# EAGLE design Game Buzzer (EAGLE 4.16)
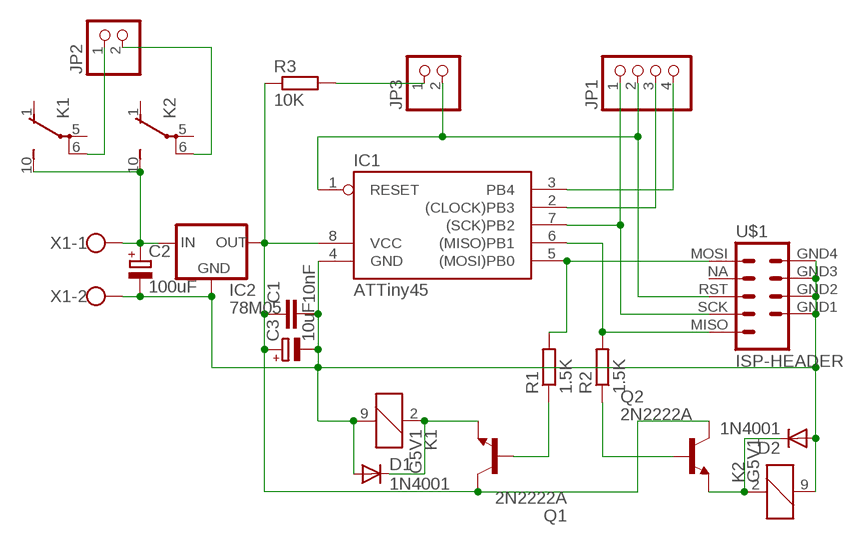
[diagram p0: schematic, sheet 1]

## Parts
C1  10nF  C-EU025-025X050  [C025-025X050]
C2  100uF  CPOL-EUE5-10.5  [E5-10,5]
C3  10uF  CPOL-EUE5-5  [E5-5]
D1  1N4001  1N4004  [DO41-10]
D2  1N4001  1N4004  [DO41-10]
IC1  ATTiny45  TINY22P  [DIL08]
IC2  78M05  78MXXS  [78MXXS]
JP1  PINHD-1X4  [1X04]
JP2  PINHD-1X2  [1X02]
JP3  PINHD-1X2  [1X02]
K1  G5V1  [G5V1]
K2  G5V1  [G5V1]
Q1  2N2222A  [TO18]
Q2  2N2222A  [TO18]
R1  1.5K  R-EU_0207/10  [0207/10]
R2  1.5K  R-EU_0207/10  [0207/10]
R3  10K  R-EU_0207/10  [0207/10]
U$1  ISP-HEADER  [ISP-HEADER]
X1  W237-102  [W237-102]

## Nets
N$1: C1.1 C3.+ IC1.8(VCC) IC2.OUT Q1.3(C) Q2.3(C) R3.1
N$2: IC1.5((MOSI)PB0) R1.2 U$1.MOSI
N$3: IC1.2((CLOCK)PB3) JP1.3
N$4: IC1.6((MISO)PB1) R2.2 U$1.MISO
N$5: IC1.7((SCK)PB2) JP1.1 U$1.SCK
N$6: IC1.1(RESET) JP1.2 JP3.2 U$1.RST(RESET)
N$7: Q1.2(B) R1.1
N$8: Q2.2(B) R2.1
N$9: D1.C K1.2 Q1.1(E)
N$10: D2.C K2.2 Q2.1(E)
N$11: C2.+ IC2.IN K1.10(2:S) K2.10(2:S) X1.1
N$12: C1.2 C2.- C3.- D1.A D2.A IC1.4(GND) IC2.GND K1.9 K2.9 U$1.GND1 U$1.GND2 U$1.GND3 U$1.GND4 X1.2
N$13: IC1.3(PB4) JP1.4
N$14: JP2.1 K1.6(2:P)
N$15: JP2.2 K2.6(2:P)
N$16: JP3.1 R3.2
Unconnected: K1.1(2:O) K1.5(2:P) K2.1(2:O) K2.5(2:P) U$1.NA

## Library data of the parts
C1 = rcl:C-EU: CAPACITOR, European symbol
C2 C3 = rcl:CPOL-EU: POLARIZED CAPACITOR, European symbol
D1 D2 = diode:1N4004: DIODE
IC1 = atmel:TINY22: MICROCONTROLLER 1K ROM 128 bytes RAM 128 bytes EEPROM
IC2 = v-reg:78MXXS: VOLTAGE REGULATOR
JP1 = pinhead:PINHD-1X4: PIN HEADER
JP2 JP3 = pinhead:PINHD-1X2: PIN HEADER
K1 K2 = relay:G5V1: RELAY 1 x switch, 0.5 A/125 V AC, 1 A/24 V DC , Omron
Q1 Q2 = transistor-npn:2N2222*: NPN Transistor
R1-R3 = rcl:R-EU_: RESISTOR, European symbol
U$1 = Williams:ISP-HEADER
X1 = con-wago-500:W237-102: WAGO SCREW CLAMP

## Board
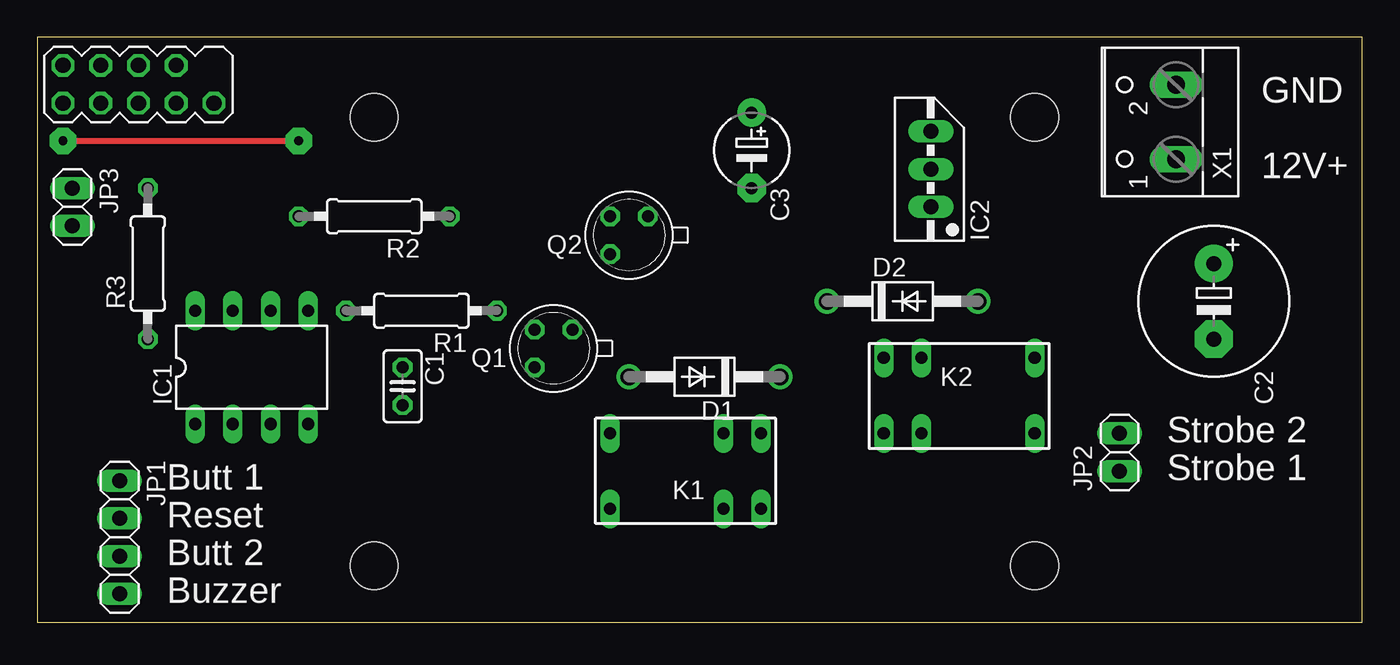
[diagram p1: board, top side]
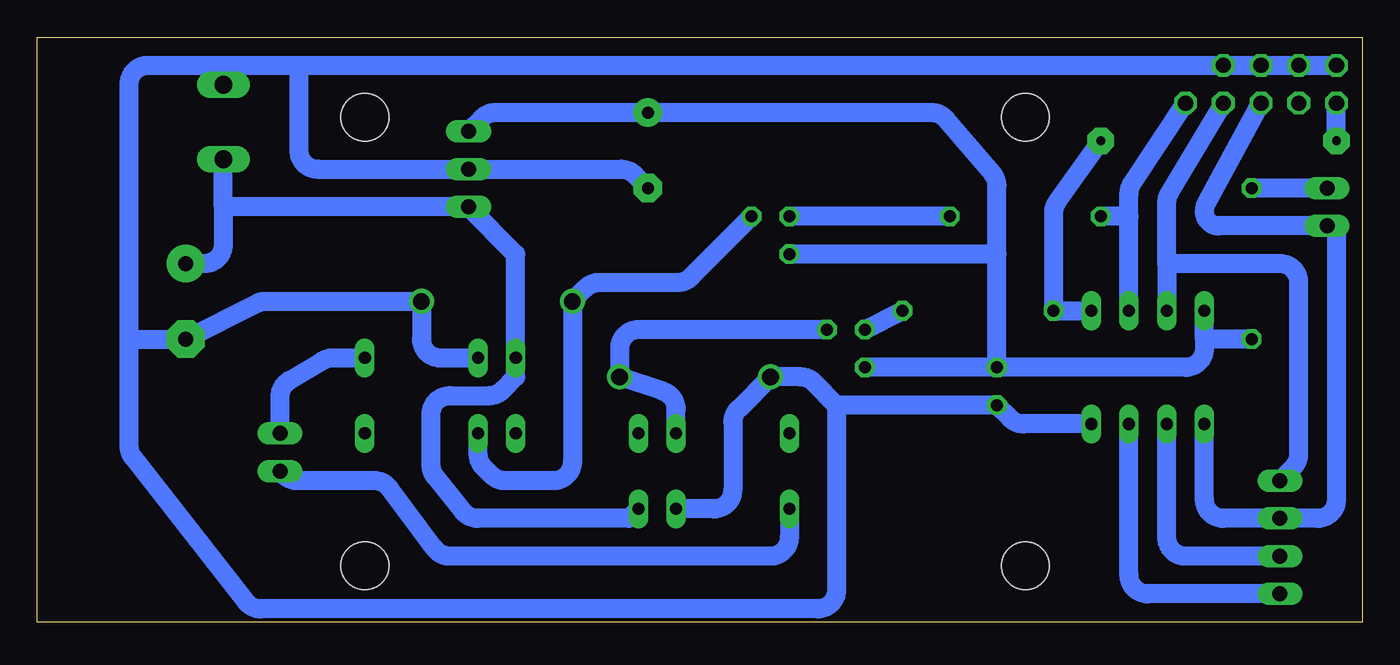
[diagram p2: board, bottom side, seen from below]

Size 89.2 x 39.36 mm. Coordinates in mm from the lower left corner, seen from the top.
Outline: 0,0 89.2,0 89.2,39.36 0,39.36 0,0
Copper layers (1*16): Top 0.035mm / dielectric 1.5mm / Bottom 0.035mm
Design rules "default": minimum track width 10mil, minimum drill 24mil, track to track 8mil, track to pad 8mil, pad to pad 8mil, via to via 8mil, smd to smd 8mil, copper to edge 40mil, drill to drill 8mil, minimum pad ring 10mil, minimum via ring 8mil, stop-mask expansion 4mil, vias tented up to drill 0mil, thermal gap 10mil
Holes 3.2 mm at 22.7,3.81 22.7,33.97 67.15,33.97 67.15,3.81
tRestrict: area 19.5,0.6 to 25.9,7; area 19.5,30.8 to 25.9,37.3; area 63.9,30.8 to 70.4,37.3; area 63.9,0.6 to 70.4,7

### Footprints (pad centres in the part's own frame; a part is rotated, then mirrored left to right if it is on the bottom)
C025-025X050 = drill 0.813 octagon: 1 -1.27,0; 2 1.27,0
E5-10,5 = drill 1.016 pad 2.54 round: + -2.54,0 | drill 1.016 pad 2.54 octagon: - 2.54,0
E5-5 = drill 0.813 pad 1.905 round: + -2.54,0 | drill 0.813 pad 1.905 octagon: - 2.54,0
DO41-10 = drill 1.118 round: A 5.08,0; C -5.08,0
DIL08 = drill 0.813 long: 1 -3.81,-3.81; 2 -1.27,-3.81; 3 1.27,-3.81; 4 3.81,-3.81; 5 3.81,3.81; 6 1.27,3.81; 7 -1.27,3.81; 8 -3.81,3.81
78MXXS = drill 1.016 long: GND 0,-2.54; IN -2.54,-2.54; OUT 2.54,-2.54
1X04 = drill 1.016 long: 1 -3.81,0; 2 -1.27,0; 3 1.27,0; 4 3.81,0
1X02 = drill 1.016 long: 1 -1.27,0; 2 1.27,0
G5V1 = drill 0.813 long: 1 -5.08,-2.54; 2 -2.54,-2.54; 5 5.08,-2.54; 6 5.08,2.54; 9 -2.54,2.54; 10 -5.08,2.54
TO18 = drill 0.813 octagon: 1 -1.27,-1.27; 2 1.27,-1.27; 3 1.27,1.27
0207/10 = drill 0.813 octagon: 1 -5.08,0; 2 5.08,0
ISP-HEADER = drill 1.016 octagon: GND1 -2.54,-1.27; GND2 0,-1.27; GND3 2.54,-1.27; GND4 5.08,-1.27; MISO -5.08,1.27; MOSI 5.08,1.27; NA 2.54,1.27; RST 0,1.27; SCK -2.54,1.27
W237-102 = drill 1.194 long: 1 -2.5,-1.27; 2 2.5,-1.27

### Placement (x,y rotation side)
C1  24.6,15.87 270 top
C2  79.21,21.59 270 top
C3  48.09,31.75 270 top
D1  44.92,16.51 180 top
D2  58.25,21.59 0 top
IC1  14.44,17.14 0 top
IC2  57.62,30.48 90 top
JP1  5.55,5.71 270 top
JP2  72.86,11.42 90 top
JP3  2.38,27.94 270 top
K1  43.65,10.15 180 top
K2  62.06,15.23 0 top
Q1  34.76,18.41 180 top
Q2  39.84,26.03 180 top
R1  25.87,20.95 180 top
R2  22.7,27.3 180 top
R3  7.45,24.12 90 top
U$1  6.82,36.19 180 top
X1  75.4,33.65 90 top

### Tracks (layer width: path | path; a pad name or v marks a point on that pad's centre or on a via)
N$1
  Bottom 1.27: 10.63,19.05 10.63,18.41 arc90 11.9,17.14 C1.1 | 10.63,19.05 IC1.8 | C1.1 24.6,24.76 | C1.1 Q1.3 | 24.6,24.76 Q2.3 | 24.6,24.76 24.6,29.37 arc-41 24.91,30.2 28.03,33.84 arc-49 28.99,34.28 C3.+ 58.36,34.28 arc-45 59.26,33.91 IC2.OUT | R3.1 10.63,19.05
N$2  (via drill 0.6 pad 1.78)
  Top 0.406: v1.74,32.38 v17.61,32.38
  Bottom 1.27: IC1.5 R1.2 20.79,27.53 arc36 20.55,28.27 v17.61,32.38 | v1.74,32.38 U$1.MOSI
N$3
  Bottom 1.27: JP1.3 11.9,4.44 arc90 13.17,5.71 IC1.2
N$4
  Bottom 1.27: IC1.6 15.71,27.3 | 15.71,27.3 15.71,28.82 arc34 15.5,29.53 U$1.MISO | 15.71,27.3 R2.2
N$5
  Bottom 1.27: 13.17,24.12 IC1.7 | 13.17,24.12 13.17,28.22 arc31 12.99,28.87 U$1.SCK | JP1.1 4.65,10.42 arc-45 4.28,11.32 4.28,22.86 arc-90 5.55,24.12 13.17,24.12
N$6
  Bottom 1.27: 1.74,26.67 9.68,26.67 arc90 10.63,27.61 arc29 10.47,28.22 U$1.RST | IC1.1 10.63,8.25 arc-90 9.36,6.98 JP1.2 3.01,6.98 arc-90 1.74,8.25 1.74,26.67 | JP3.2 1.74,26.67
N$7
  Bottom 1.27: Q1.2 R1.1
N$8
  Bottom 1.27: R2.1 Q2.2
N$9
  Bottom 1.27: Q1.1 48.73,19.68 arc-90 50,18.41 D1.C 47.06,15.52 arc72 46.19,14.32 K1.2
N$10
  Bottom 1.27: K2.2 59.52,11.32 arc-45 59.15,10.42 58.63,9.89 arc-45 57.73,9.52 54.44,9.52 arc-90 53.17,10.79 D2.C 52.28,22.48 arc45 51.38,22.86 46.08,22.86 arc-45 45.18,23.23 Q2.1
N$11
  Bottom 1.27: K1.10 49.36,6.98 59.55,6.98 arc51 60.54,7.46 62.42,9.81 arc39 62.7,10.6 62.7,13.96 arc90 61.43,15.23 58.78,15.23 arc-45 57.88,15.61 56.98,16.51 K2.10 56.98,24.76 IC2.IN 76.67,27.94 | 76.67,27.94 76.67,25.39 arc90 77.94,24.12 C2.+ | 76.67,27.94 X1.1
N$12
  Bottom 1.27: U$1.GND4 U$1.GND3 U$1.GND2 U$1.GND1 71.59,37.46 | 76.67,37.46 71.59,37.46 | 83.02,19.05 83.02,36.19 arc90 81.75,37.46 76.67,37.46 | IC1.4 22.8,13.33 arc45 23.7,13.7 C1.2 35.39,14.6 | 76.67,37.46 X1.2 | 83.02,19.05 C2.- 74.4,21.45 arc27 73.83,21.59 D2.A 63.33,19.05 arc-90 62.06,17.78 K2.9 | 71.59,37.46 71.59,31.75 arc-90 70.32,30.48 IC2.GND 49.89,30.48 arc45 48.99,30.1 C3.- | K1.9 43.65,7.62 arc-90 42.38,8.88 42.38,13.44 arc45 42.01,14.34 D1.A 37.83,16.51 arc45 36.93,16.13 35.39,14.6 | 35.39,14.6 35.39,2.15 arc90 36.66,0.88 74.15,0.88 arc52 75.15,1.37 82.75,11.08 arc38 83.02,11.86 83.02,19.05
N$13
  Bottom 1.27: JP1.4 14.44,1.9 arc90 15.71,3.17 IC1.3
N$14
  Bottom 1.27: K1.6 38.57,5.71 arc90 39.84,4.44 61.43,4.44 arc53 62.45,4.95 65.49,9.01 arc-53 66.51,9.52 71.7,9.52 arc45 72.6,9.89 JP2.1
N$15
  Bottom 1.27: JP2.2 72.86,15.15 arc59 72.24,16.24 69.99,17.59 arc31 69.33,17.78 K2.6
N$16
  Bottom 1.27: JP3.1 R3.2

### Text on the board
tPlace: GND | 12V+ | Strobe 2 | Strobe 1 | Butt 1 | Reset | Butt 2 | Buzzer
